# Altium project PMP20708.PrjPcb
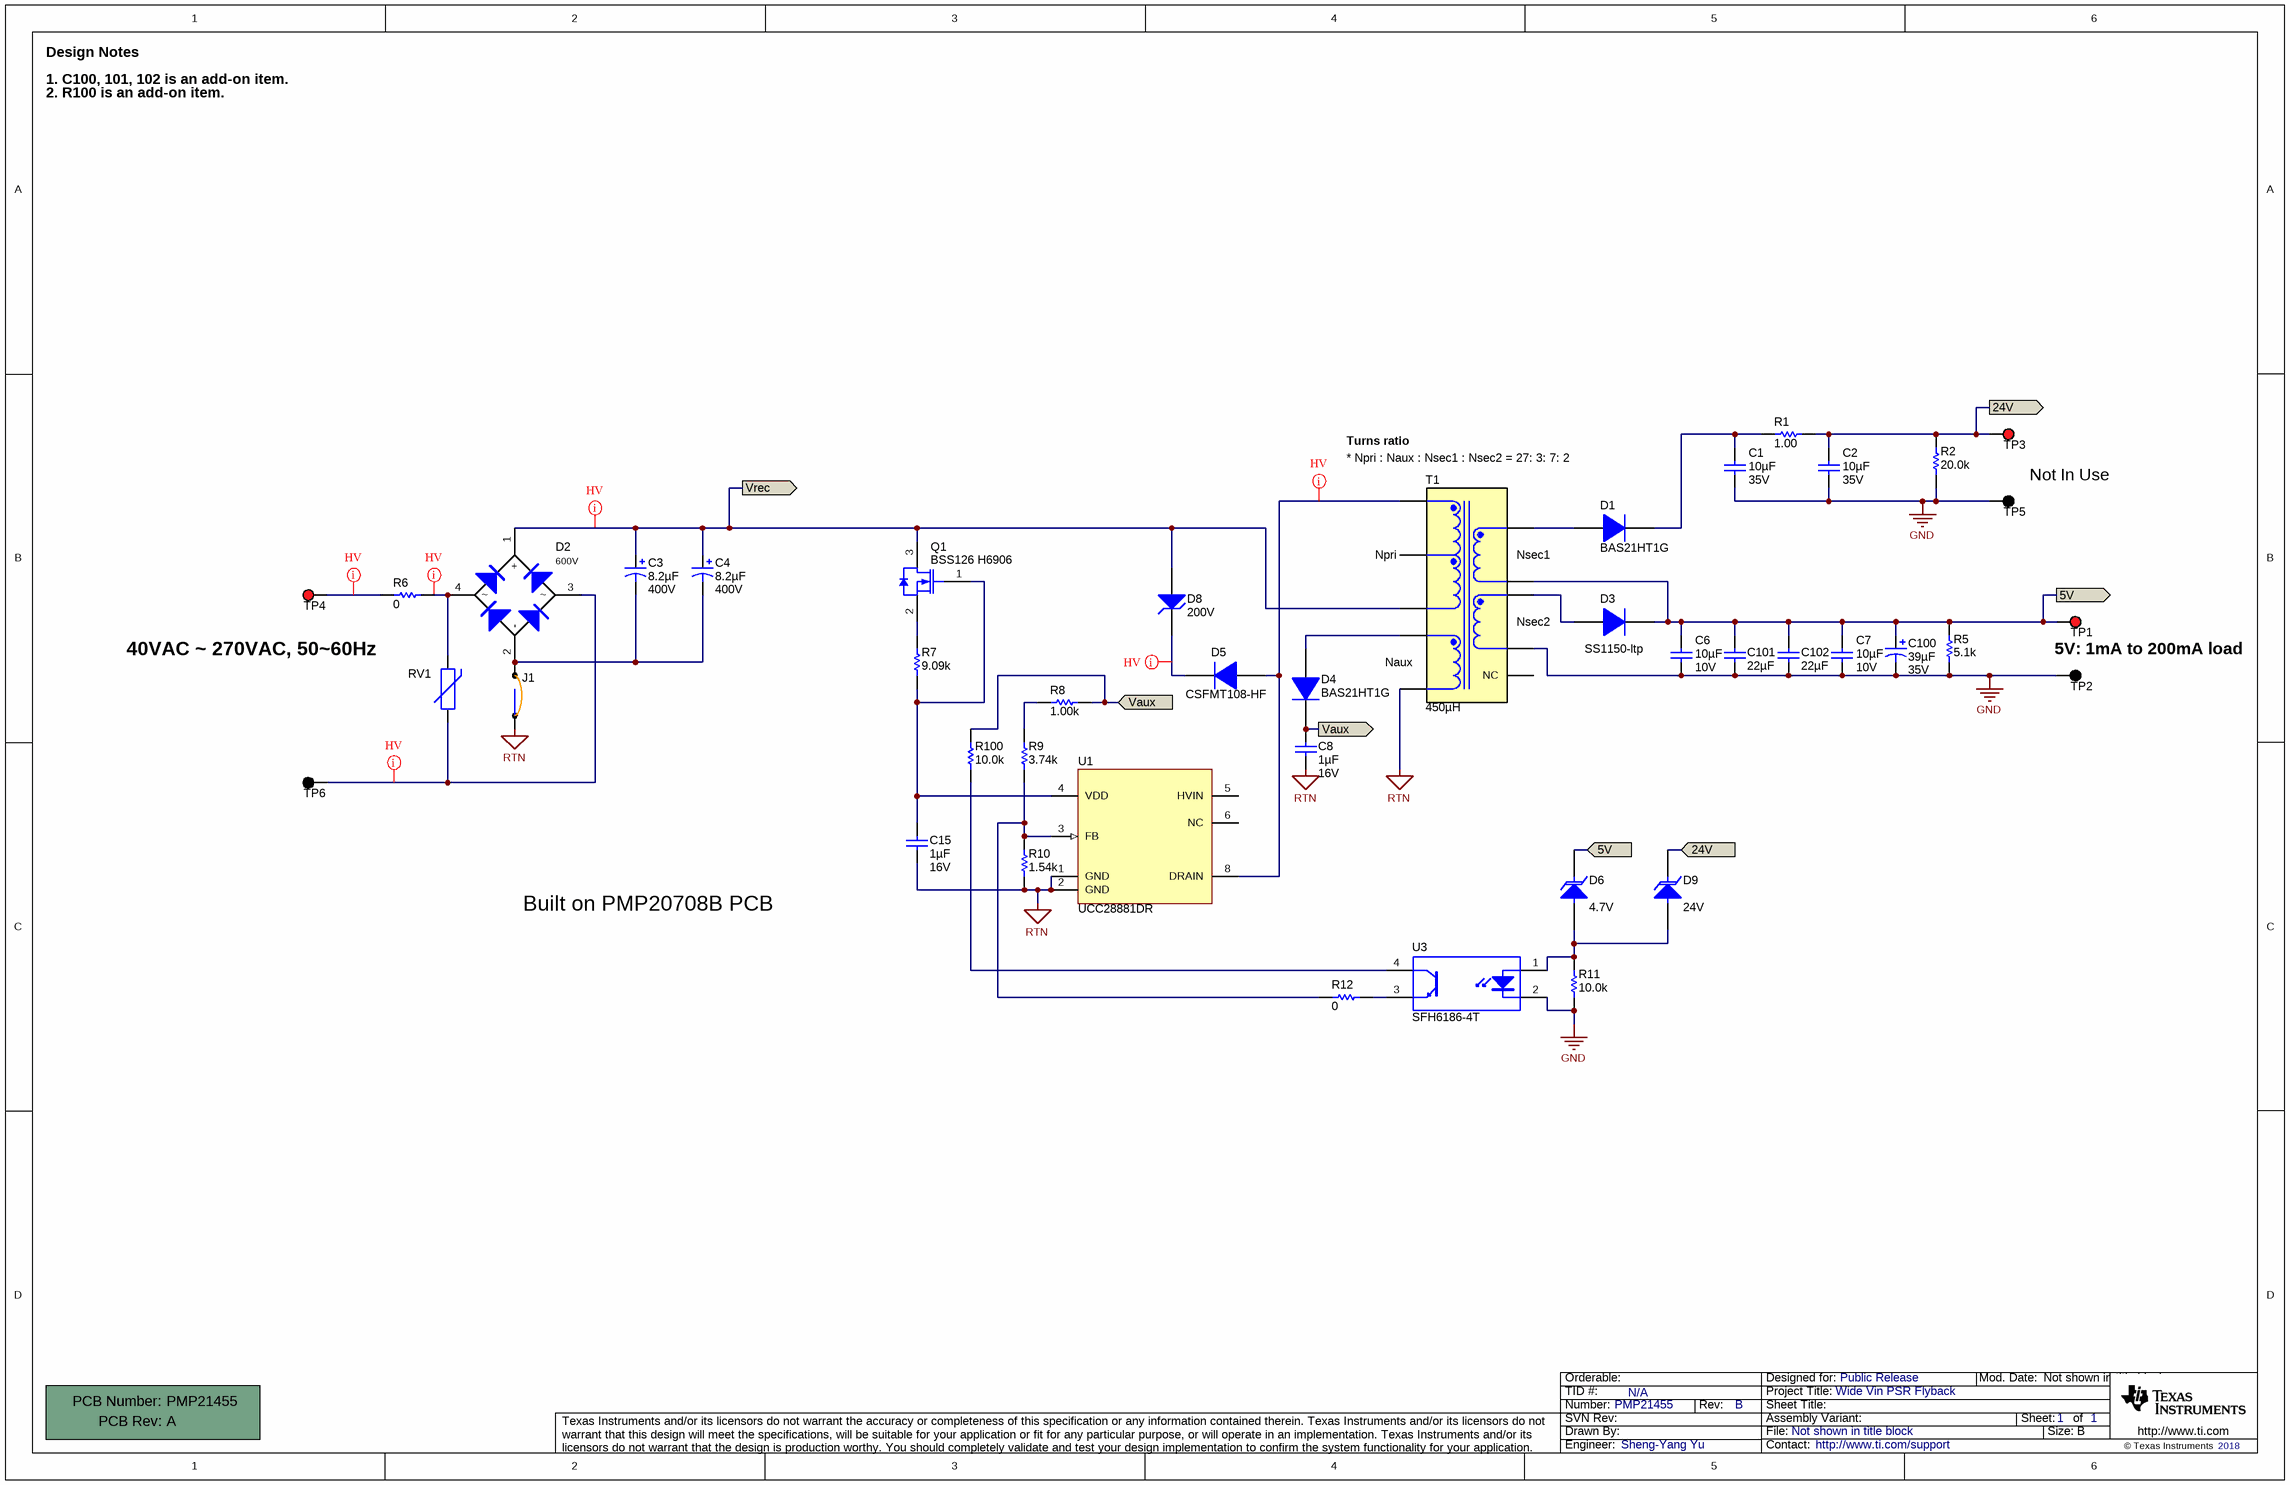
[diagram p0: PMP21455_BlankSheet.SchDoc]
TID: N/A; TechSupport: http://www.ti.com/support; SCH_Rev: B; PRJ_Title: Wide Vin PSR Flyback; PRJ_Number: PMP21455; PRJ_Engineer: Sheng-Yang Yu; PRJ_Customer: Public Release; PCB_Rev: A; PCB_Layout: Sheng-Yang Yu; CopyrightYear: 2018
1 sheet, 43 parts. Net scope: flat (ports and power ports of the same name join across sheets).
Board file: PMP21455_PCB.PcbDoc

## Sheet PMP21455_BlankSheet.SchDoc
size 431 x 279 mm; Date: Not shown in title block; ApprovedBy: Not shown in title block; CheckedBy: Not shown in title block; Author: Not shown in title block; CompanyName: Not shown in title block; Engineer: Not shown in title block; Organization: Not shown in title block; Address1: Not shown in title block; Address2: Not shown in title block; Address3: Not shown in title block; Address4: Not shown in title block; DocumentNumber: 1; Revision: Use project parameter SCH_Rev; SheetNumber: 1; SheetTotal: 1; PageSetup: Record=PageOptions¦CenterHorizontal=True¦CenterVertical=True¦PrintScale=1.00¦XCorrection=1.00¦YCorrection=1.00¦PrintKind=0¦BorderSize=5000000¦LeftOffset=0¦BottomOffset=0¦Orientation=2¦PaperLength=1000¦PaperWidth=1000¦Scale=100¦PaperSource=15¦PrintQuality=600¦MediaType=1¦DitherType=10¦PaperKind=Letter¦PrintScaleMode=1

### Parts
!PCB1  Printed Circuit Board  (value not drawn)  (mechanical)
C1  ValueDisplayed: 10µF  Value2: 35V  [0805_HV]  (hidden comment: C2012X5R1V106K085AC)
C2  ValueDisplayed: 10µF  Value2: 35V  [0805_HV]  (hidden comment: C2012X5R1V106K085AC)
C3  ValueDisplayed: 8.2µF  Value2: 400V  [ULV_1000x1350]  (hidden comment: ULR2G8R2MNL1GS)
C4  ValueDisplayed: 8.2µF  Value2: 400V  [ULV_1000x1350]  (hidden comment: ULR2G8R2MNL1GS)
C6  ValueDisplayed: 10µF  Value2: 10V  [0805_HV]  (hidden comment: C2012X7R1A106K125AC)
C7  ValueDisplayed: 10µF  Value2: 10V  [0805_HV]  (hidden comment: C2012X7R1A106K125AC)
C8  ValueDisplayed: 1µF  Value2: 16V  [0402]  (hidden comment: C1005X6S1C105K050BC)
C15  ValueDisplayed: 1µF  Value2: 16V  [0402]  (hidden comment: C1005X6S1C105K050BC)
C100  ValueDisplayed: 39µF  Value2: 35V  [FC_630x1120]  (hidden comment: EEU-FC1V390)
C101  ValueDisplayed: 22µF  [1206_180]  (hidden comment: GRM31CR61E226KE15L)
C102  ValueDisplayed: 22µF  [1206_180]  (hidden comment: GRM31CR61E226KE15L)
D1  BAS21HT1G  [SOD-323]
D2  Value2: 600V  [MiniDIP]  (hidden comment: RH06-T)
D3  BAS21HT1G  [SOD-323]  (value not drawn)
D4  BAS21HT1G  [SOD-323]
D5  CSFMT108-HF  [SOD-123H]
D6  value 4.7V  [SOD-323-Bi]  (hidden comment: VDZT2R4.7B)
D8  value 200V  [DO-219AB]  (hidden comment: BZD27C200P-E3-08)
D9  value 24V  [SOD-323-Bi]  (hidden comment: TFZVTR24B)
J1  923345-03-C  [923345-03-C]  (value not drawn)
Q1  BSS126 H6906  [SOT-23]
R1  ValueDisplayed: 1.00  [0603]  (hidden comment: CRCW06031R00FKEA)
R2  ValueDisplayed: 20.0k  [0402]  (hidden comment: CRCW040220K0FKED)
R5  ValueDisplayed: 5.1k  [0402]  (hidden comment: CRCW04025K10JNED)
R6  ValueDisplayed: 0  [1206]  (hidden comment: CRCW12060000Z0EA)
R7  ValueDisplayed: 9.09k  [0402]  (hidden comment: CRCW04029K09FKED)
R8  ValueDisplayed: 1.00k  [0402]  (hidden comment: CRCW04021K00FKED)
R9  ValueDisplayed: 3.74k  [0402]  (hidden comment: CRCW04023K74FKED)
R10  ValueDisplayed: 1.54k  [0402]  (hidden comment: CRCW04021K54FKED)
R11  ValueDisplayed: 10.0k  [0402]  (hidden comment: CRCW040210K0FKED)
R12  ValueDisplayed: 0  [0805_HV]  (hidden comment: CRCW08050000Z0EA)
R100  ValueDisplayed: 10.0k  [0402]  (hidden comment: CRCW040210K0FKED)
RV1  B72207S301K111  [VAR_S10K275E2]  (value not drawn)
T1  ValueDisplayed: 450µH  [Wurth_750316908]  (hidden comment: 750316908)
TP1  5000  [Keystone5000]  (value not drawn)
TP2  5001  [Keystone5001]  (value not drawn)
TP3  5000  [Keystone5000]  (value not drawn)
TP4  5000  [Keystone5000]  (value not drawn)
TP5  5001  [Keystone5001]  (value not drawn)
TP6  5001  [Keystone5001]  (value not drawn)
U1  UCC28881DR  [D0007A_N]
U3  SFH6186-4T  [SMD-4]

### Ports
5V (in), 5V (out), 24V (in), 24V (out), Vaux (in), Vaux (out), Vrec (out)

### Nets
GND: C1.2 C2.2 C6.1 C7.1 C100.2(-) C101.1 C102.1 R2.1 R5.1 R11.1 T1.6 TP2.1 TP5.1 U3.2(K)
RTN: C8.2 C15.1 J1.2 R10.1 T1.2 U1.1(GND) U1.2(GND)
5V: C6.2 C7.2 C100.1(+) C101.2 C102.2 D3.1(K) D6.1(K) R5.2 T1.7 TP1.1 ; port 5V
24V: C2.1 D9.1(K) R1.2 R2.2 TP3.1 ; port 24V
Vaux: C8.1 D4.1(K) R8.2 R100.2 ; port Vaux
Vrec: C3.1(+) C4.1(+) D2.1(+) D8.2(A) Q1.3(D) T1.5 ; port Vrec
NetC1_1: C1.1 D1.1(K) R1.1
NetC3_2: C3.2(-) C4.2(-) D2.2(-) J1.1
NetC15_2: C15.2 Q1.1(G) R7.1 U1.4(VDD)
NetD1_2: D1.2(A) T1.9
NetD2_3: D2.3 RV1.1 TP6.1
NetD2_4: D2.4 R6.2 RV1.2
NetD3_2: D3.2(A) T1.8
NetD4_2: D4.2(A) T1.1
NetD5_1: D5.1(K) D8.1(K)
NetD5_2: D5.2(A) T1.3 U1.8(DRAIN)
NetD6_2: D6.2(A) D9.2(A) R11.2 U3.1(A)
NetQ1_2: Q1.2(S) R7.2
NetR6_1: R6.1 TP4.1
NetR8_1: R8.1 R9.2
NetR9_1: R9.1 R10.2 R12.1 U1.3(FB)
NetR12_2: R12.2 U3.3(E)
NetR100_1: R100.1 U3.4(C)

Not connected (* = marked no-connect by the designer): T1 4 10(NC); U1 5(HVIN) 6(NC)

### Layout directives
net class HV: NetD2_3, NetD2_4, NetD5_1, NetD5_2, NetR6_1, Vrec

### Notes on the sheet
- Design Notes
- 1. C100, 101, 102 is an add-on item.
- 2. R100 is an add-on item.
- Turns ratio
- (near T1) * Npri : Naux : Nsec1 : Nsec2 = 27: 3: 7: 2
- Not In Use
- (near T1) Npri
- (near T1) Nsec1
- (near T1) Nsec2
- 40VAC ~ 270VAC, 50~60Hz
- (near T1) Naux
- (near D3) SS1150-ltp
- 5V: 1mA to 200mA load
- Built on PMP20708B PCB

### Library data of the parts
!PCB1 = PCB: Manufacturer: Any; PartNumber: PMP21455; SymbolCreator: a0412235
C1 C2 = C2012X5R1V106K085AC: CAP, CERM, 10 µF, 35 V, +/- 10%, X5R, 0805; Manufacturer: TDK; Polarized: N; CompType: Capacitor; Value: 10uF; U/M: EA; Cap_F: 0.00001; Tolerance_%: 10; ESR_ohm: 0.002818; Value1: 0.002818 ohm; VDC_V: 35; IRMS_A: 3.88676; TaMin_C: -55; TaMax_C: 85; Cap_Case: 0805; SizeArea_mm2: 2.5; SizeAreaWB_mm2: 6.75; SizeX_mm: 2; SizeY_mm: 1.25; SizeZ_mm: 1.45; AEC Category: Q200
C3 C4 = ULV2G100MNL1GS: CAP ALUM 8.2UF 20% 400V SMD; Manufacturer: Nichicon; Polarized: Y; CompType: Capacitor; U/M: EA; Cap_F: 0.00001; Tolerance_%: 20; Value1: Unknown; VDC_V: 400; IRMS_A: 0.055; TaMin_C: -40; TaMax_C: 105; Cap_Case: 10x13.5mm; AEC Category: Q200; AEC Qualified: N
C6 C7 = C2012X7R1A106K125AC: CAP, CERM, 10 µF, 10 V, +/- 10%, X7R, 0805; Manufacturer: TDK; Polarized: N; CompType: Capacitor; Value: 10uF; U/M: EA; Cap_F: 0.00001; Tolerance_%: 10; ESR_ohm: 0.001063; Value1: 0.001063 ohm; IRMS_A: 6.32908; TaMin_C: -55; TaMax_C: 125; Cap_Case: 0805; SizeArea_mm2: 2.5; SizeAreaWB_mm2: 6.75; SizeX_mm: 2; SizeY_mm: 1.25; SizeZ_mm: 1.45; AEC Category: Q200; Green_Lifecycle: Active; Green_REACh: Passed
C8 = C1005X6S1C105K050BC: CAP, CERM, 1 µF, 16 V,+/- 10%, X6S, 0402; Manufacturer: TDK; Polarized: N; CompType: Capacitor; Value: 1uF; U/M: EA; Cap_F: 0.000001; Tolerance_%: 10; ESR_ohm: 0.011416; Value1: 0.011416 ohm; VDC_V: 16; IRMS_A: 1.483; TaMin_C: -55; TaMax_C: 105; SizeArea_mm2: 0.5; SizeAreaWB_mm2: 3; SizeX_mm: 1; SizeZ_mm: 0.6; AEC Category: Q200
C15 = C1005X6S1C105K050BC: CAP, CERM, 1 µF, 16 V, +/- 10%, X6S, 0402; Manufacturer: TDK; Polarized: N; CompType: Capacitor; Value: 1uF; U/M: EA; Cap_F: 0.000001; Tolerance_%: 10; ESR_ohm: 0.011416; Value1: 0.011416 ohm; VDC_V: 16; IRMS_A: 1.483; TaMin_C: -55; TaMax_C: 105; SizeArea_mm2: 0.5; SizeAreaWB_mm2: 3; SizeX_mm: 1; SizeZ_mm: 0.6; AEC Category: Q200
C100 = EEU-FC1V470: CAP ALUM 39UF 20% 35V RADIAL; Manufacturer: Panasonic; Polarized: Y; CompType: Capacitor; U/M: EA; Cap_F: 0.000047; Tolerance_%: 20; Value1: Unknown; VDC_V: 35; IRMS_A: 0.29; TaMin_C: -55; TaMax_C: 105; Cap_Case: 6.3x11.2mm; SizeAreaWB_mm2: 68.89; SizeArea_mm2: 39.69; SizeX_mm: 6.3; SizeZ_mm: 12.2; AEC Category: Q200; AEC Grade: 2
C101 C102 = GRM31CR61E226KE15L: CAP, CERM, 22 µF, 25 V,+/- 10%, X5R, 1206; Manufacturer: MuRata; Polarized: N; CompType: Capacitor; Value: 22uF; U/M: EA; Cap_F: 0.000022; Tolerance_%: 10; VDC_V: 25; Value2: 25V; TaMin_C: -55; TaMax_C: 85; Cap_Case: 1206; SizeArea_mm2: 5.12; SizeAreaWB_mm2: 10.92; SizeX_mm: 3.2; SizeY_mm: 1.6; SizeZ_mm: 1.8; AEC Category: Q200; Green_Lifecycle: Active; Green_REACh: Passed
D1 D3 D4 = BAS20HT1G: DIODE GEN PURP 250V 200MA SOD323; Manufacturer: ON Semiconductor; U/M: EA; Io_A: 0.2; TJmax_C: 150; Type: Switching; SizeAreaWB_mm2: 8.695; SizeArea_mm2: 3.645; SizeX_mm: 2.7; SizeY_mm: 1.35; SizeZ_mm: 1; AEC Category: Q101; AEC Qualified: Y; Green_Lifecycle: Not Set; Green_REACh: Incomplete
D2 = RH06-T: Diode, Switching-Bridge, 600V, 0.5A, MiniDIP; Manufacturer: Diodes Inc.; Value: 1.15V; U/M: EA; Vf_V: 1.15; Io_A: 0.5; Vr_V: 600; TJmax_C: 150
D5 = CSFMT108-HF: Diode, Superfast Rectifier, 600 V, 1 A, 3.5x1.6mm; Manufacturer: Comchip Technology; U/M: EA; Vf_V: 1.7; Value: 600V; Value1: 1A; Value2: 1.7V; Io_A: 1; Vr_V: 600; TJmax_C: 150; SizeAreaWB_mm2: 11.7; SizeArea_mm2: 5.6; SizeX_mm: 3.5; SizeY_mm: 1.6; AEC Category: Q101; AEC Qualified: N; Green_Lifecycle: Not Set; Green_REACh: Incomplete
D6 = PESD24VL1BA,115: DIODE ZENER 4.7V 100MW VMD2; Manufacturer: Rohm Semiconductor; CompType: TVS; U/M: EA; Vr_V: 4.7; Value1: W; AEC Category: Q101; AEC Qualified: N
D8 = BZD27C200P-E3-08: Diode, Zener, 200 V, 800 mW, AEC-Q101, DO-219AB; Manufacturer: Vishay-Semiconductor; SymbolCreator: a0412235; U/M: EA; Power_W: 0.8; Vz_V: 200; Value1: 0.8W; RJA_CperW: 180; SizeAreaWB_mm2: 13.16; SizeArea_mm2: 6.66; SizeX_mm: 3.7; SizeY_mm: 1.8; SizeZ_mm: 1.08; AEC Category: Q101; AEC Qualified: Y
D9 = PESD24VL1BA,115: Zener Diode 500mW ±3% Surface Mount SOD-323HE; Manufacturer: Rohm Semiconductor; CompType: TVS; U/M: EA; Value1: W; AEC Category: Q101; AEC Qualified: N
J1 = 923345-03-C: Jumper Wire, 300mil spacing, Orange, pkg of 200; Manufacturer: 3M; SymbolCreator: a0412235; Green_Lifecycle: Active; Green_REACh: Passed
Q1 = BSS126 H6906: MOSFET, N-CH, 600 V, 0.021 A, AEC-Q101, SOT-23; Manufacturer: Infineon Technologies; Alternate Manufacturer: None; SymbolCreator: a0412235; U/M: EA; ChType: N; Value: 600V; VdsMax_V: 600; Value1: ? ohm; Value2: 1.4 nC; QgTyp_nC: 1.4; Vgs_V: 20; IdsMax_A: 0.021; SizeAreaWB_mm2: 14; SizeArea_mm2: 7.5; SizeX_mm: 2.5; SizeY_mm: 3; SizeZ_mm: 1.1; AEC Category: Q101; AEC Qualified: Y
R1 = CRCW06031R00FKEA: RES, 1.00, 1%, 0.1 W, 0603; Manufacturer: Vishay-Dale; CompType: Resistor; Value: 1.00; Res_ohm: 1; Value_Code: 1R00; Power_W: 0.1; Value2: 0.1W; VDC_V: 75; TempCo: 100 ppm/C; SizeArea_mm2: 1.28; SizeX_mm: 1.6; SizeY_mm: 0.8; EIA_Code: E96; U/M: EA; AEC Category: Q200; Green_Lifecycle: Active; Green_REACh: Passed
R2 = CRCW040220K0FKED: RES, 20.0 k, 1%, 0.063 W, 0402; Manufacturer: Vishay-Dale; CompType: Resistor; Value: 20.0k; Res_ohm: 20000; Value_Code: 20k0; Tolerance_%: 1; Power_W: 0.063; Value2: 0.063W; VDC_V: 50; TempCo: 100 ppm/C; SizeArea_mm2: 0.5; SizeZ_mm: 0.6; EIA_Code: E96; U/M: EA; AEC Category: Q200
R5 = CRCW04025K10JNED: RES, 5.1 k, 5%, 0.063 W, 0402; Manufacturer: Vishay-Dale; CompType: Resistor; Value: 5.1k; Res_ohm: 5100; Value_Code: 5k10; Tolerance_%: 5; Power_W: 0.063; Value2: 0.063W; VDC_V: 50; TempCo: 200 ppm/C; SizeArea_mm2: 0.5; SizeX_mm: 1; SizeZ_mm: 0.6; EIA_Code: E24; U/M: EA; AEC Category: Q200
R6 = CRCW12060000Z0EA: RES, 0, 5%, 0.25 W, 1206; Manufacturer: Vishay-Dale; CompType: Resistor; Value: 0; Value_Code: 0000; Tolerance_%: 5; Power_W: 0.25; Value2: 0.25W; VDC_V: 200; TempCo: 200 ppm/C; SizeArea_mm2: 5.12; SizeX_mm: 3.2; SizeY_mm: 1.6; SizeZ_mm: 1.35; EIA_Code: E24; U/M: EA; AEC Category: Q200; Green_Lifecycle: Active; Green_REACh: Passed
R7 = CRCW04029K09FKED: RES, 9.09 k, 1%, 0.063 W, 0402; Manufacturer: Vishay-Dale; CompType: Resistor; Value: 9.09k; Res_ohm: 9090; Value_Code: 9k09; Tolerance_%: 1; Power_W: 0.063; Value2: 0.063W; VDC_V: 50; TempCo: 100 ppm/C; SizeArea_mm2: 0.5; SizeZ_mm: 0.6; EIA_Code: E96; U/M: EA; AEC Category: Q200
R8 = CRCW04021K00FKED: RES, 1.00 k, 1%, 0.063 W, 0402; Manufacturer: Vishay-Dale; CompType: Resistor; Value: 1.00k; Res_ohm: 1000; Value_Code: 1k00; Tolerance_%: 1; Power_W: 0.063; Value2: 0.063W; VDC_V: 50; TempCo: 100 ppm/C; SizeArea_mm2: 0.5; SizeZ_mm: 0.6; EIA_Code: E96; U/M: EA; AEC Category: Q200; Green_Lifecycle: Active; Green_REACh: Passed
R9 = CRCW04023K74FKED: RES, 3.74 k, 1%, 0.063 W, 0402; Manufacturer: Vishay-Dale; CompType: Resistor; Value: 3.74k; Res_ohm: 3740; Value_Code: 3k74; Tolerance_%: 1; Power_W: 0.063; Value2: 0.063W; VDC_V: 50; TempCo: 100 ppm/C; SizeArea_mm2: 0.5; SizeZ_mm: 0.6; EIA_Code: E96; U/M: EA; AEC Category: Q200
R10 = CRCW04021K54FKED: RES, 1.54 k, 1%, 0.063 W, 0402; Manufacturer: Vishay-Dale; CompType: Resistor; Value: 1.54k; Res_ohm: 1540; Value_Code: 1k54; Tolerance_%: 1; Power_W: 0.063; Value2: 0.063W; VDC_V: 50; TempCo: 100 ppm/C; SizeArea_mm2: 0.5; SizeZ_mm: 0.6; EIA_Code: E96; U/M: EA; AEC Category: Q200
R11 = CRCW040210K0FKED: RES, 10.0 k, 1%, 0.063 W, 0402; Manufacturer: Vishay-Dale; CompType: Resistor; Value: 10.0k; Res_ohm: 10000; Value_Code: 10k0; Tolerance_%: 1; Power_W: 0.063; Value2: 0.063W; VDC_V: 50; TempCo: 100 ppm/C; SizeArea_mm2: 0.5; SizeZ_mm: 0.6; EIA_Code: E96; U/M: EA; AEC Category: Q200
R12 = CRCW08050000Z0EA: RES, 0, 5%, 0.125 W, 0805; Manufacturer: Vishay-Dale; CompType: Resistor; Value: 0; Value_Code: 0000; Tolerance_%: 5; Power_W: 0.125; Value2: 0.125W; VDC_V: 150; TempCo: 200 ppm/C; SizeArea_mm2: 2.5; SizeX_mm: 2; SizeY_mm: 1.25; SizeZ_mm: 1.45; EIA_Code: E24; U/M: EA; AEC Category: Q200
R100 = CRCW040210K0FKED: RES, 10.0 k, 1%, 0.063 W, 0402; Manufacturer: Vishay-Dale; CompType: Resistor; Value: 10.0k; Res_ohm: 10000; Value_Code: 10k0; Tolerance_%: 1; Power_W: 0.063; Value2: 0.063W; VDC_V: 50; TempCo: 100 ppm/C; SizeArea_mm2: 0.5; SizeZ_mm: 0.6; EIA_Code: E96; U/M: EA; AEC Category: Q200; Green_Lifecycle: Active; Green_REACh: Passed
RV1 = S10K275E2: VARISTOR 470V 1.2KA DISC 7MM; Manufacturer: EPCOS Inc; SymbolCreator: a0412235; Value: 423V
T1 = 750316908: Transformer, 450 uH, SMT; Manufacturer: Wurth Elektronik; SymbolCreator: Altium; Value: 450uH; DCR_ohm: 1.2; Lp: 450; Ind_H: 0.00045; LeakageInd_H: 3E-6; Ns1toNp: 0.26; Ns2toNp: 0.074; Rsec1_ohm: 0.3; Rsec2_ohm: 0.09; SizeAreaWB_mm2: 309.0552; SizeArea_mm2: 242.2952; SizeX_mm: 17.66; SizeY_mm: 13.72; SizeZ_mm: 10.5
TP1 TP3 TP4 = 5000: Test Point, Miniature, Red, TH; Manufacturer: Keystone; CompType: Test Point Loop; ContactFinish: Silver
TP2 TP5 TP6 = 5001: Test Point, Miniature, Black, TH; Manufacturer: Keystone; CompType: Test Point Loop; ContactFinish: Silver
U1 = UCC28880DR: 700-V Lowest Quiescent Current Off-Line Switcher, D0007A; Manufacturer: Texas Instruments; SymbolCreator: a0411947; CompType: IC; U/M: EA
U3 = SFH6156-2T: OPTOISOLATOR 5.3KV TRANS 4SMD; Manufacturer: Vishay-Semiconductor; CTR (Min): 63%; CTR (Max): 125%; Voltage_Isolation_Vrms: 5300V; CompType: Optocoupler

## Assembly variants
001: not fitted D9 R8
